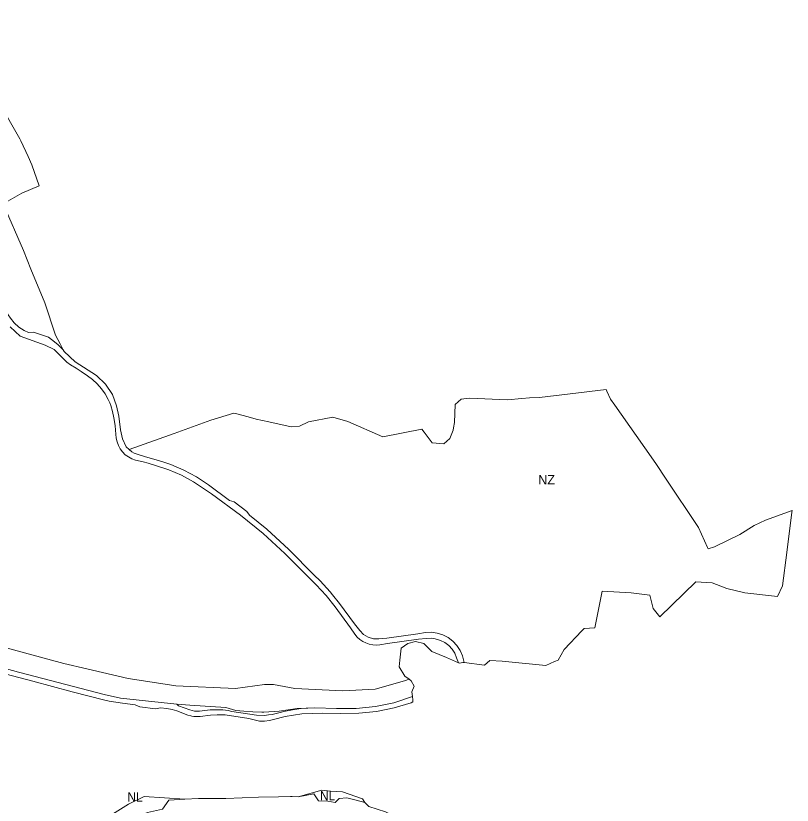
# Model space of a CAD drawing. Extents: x -650451 to -642268, y -1075216 to -1066610.
# Drawn here: x -645020 to -644023, y -1068995 to -1067980 of the extents above; entities that cross this region are included whole.
import ezdxf

# ---------------------------------------------------------------- set-up
doc = ezdxf.new("R2010")
doc.units = 0
doc.header["$LTSCALE"] = 4.8
for name, color, linetype, lineweight in [('15', 7, 'Continuous', 13), ('25', 7, 'Continuous', 13), ('45', 7, 'Continuous', 13), ('46', 7, 'Continuous', 13), ('47', 7, 'Continuous', 13), ('48', 7, 'Continuous', 13)]:
    doc.layers.add(name, color=color, linetype=linetype, lineweight=lineweight)
doc.layers.add('62', color=7, linetype='Continuous')

msp = doc.modelspace()

# ---------------------------------------------------------------- linework, layer by layer
at = {"layer": '15'}
for points in [[(-645212.831, -1068022.262), (-645216.33, -1068029.45), (-645210.19, -1068049.9), (-645200.78, -1068069.33), (-645154.68, -1068150.75), (-645140.99, -1068174.92), (-645123.29, -1068207.28), (-645106.55, -1068240.15), (-645098.61, -1068256.33), (-645091.6, -1068269.57), (-645083.99, -1068282.08), (-645035.86, -1068356.25), (-645030.2, -1068364.48), (-645027.23, -1068368.85), (-645022.34, -1068375.11), (-645016.44, -1068380.44), (-645009.72, -1068384.69), (-645003.98, -1068387.18), (-644997.7, -1068387.1), (-644978.39, -1068393.26), (-644970.72, -1068399.33), (-644966.17, -1068403.25), (-644959.42, -1068409.51)], [(-644451.72, -1068811.85), (-644454.22, -1068805.29), (-644456.69, -1068799.46), (-644460.09, -1068794.2), (-644464.36, -1068789.61), (-644469.35, -1068785.83), (-644474.92, -1068782.96), (-644481.87, -1068780.8), (-644487.12, -1068780.31), (-644493.45, -1068780.61), (-644503.36, -1068781.54), (-644543.14, -1068786.88), (-644553.01, -1068788.71), (-644557.54, -1068789.02), (-644562.07, -1068788.72), (-644566.53, -1068787.81), (-644570.82, -1068786.31), (-644574.88, -1068784.25), (-644578.63, -1068781.68), (-644582, -1068778.62), (-644584.92, -1068775.15), (-644590.45, -1068766.78), (-644610.23, -1068739.86), (-644621.86, -1068725.22), (-644634.57, -1068711.51), (-644674.76, -1068671.3), (-644702.58, -1068645.52), (-644731.96, -1068622.17), (-644769.24, -1068594.82), (-644783.35, -1068585.07), (-644792.14, -1068579.21), (-644807.7, -1068570.75), (-644823.96, -1068563.74), (-644840.81, -1068558.21), (-644850.38, -1068555.38), (-644857.02, -1068553.54), (-644866.81, -1068551.32), (-644871.47, -1068549.65), (-644875.84, -1068547.31), (-644879.83, -1068544.36), (-644883.35, -1068540.86), (-644886.32, -1068536.89), (-644888.68, -1068532.52), (-644890.38, -1068527.86), (-644891.38, -1068523.02), (-644892.19, -1068513.01), (-644893.01, -1068506.77), (-644894.55, -1068496.92), (-644896.06, -1068488.82), (-644898.42, -1068480.97), (-644899.73, -1068477.88), (-644901.61, -1068473.42), (-644905.59, -1068466.26), (-644910.32, -1068459.56), (-644915.73, -1068453.41), (-644921.78, -1068447.88), (-644928.42, -1068443), (-644936.62, -1068437.33), (-644942.9, -1068433.22), (-644950.19, -1068428.86), (-644954.98, -1068425.33), (-644959.35, -1068421.29), (-644971.12, -1068409.35), (-644982.58, -1068403.83), (-645014.95, -1068392.17), (-645027.82, -1068380.21)], [(-644959.42, -1068409.51), (-644958.31, -1068411.62), (-644944.04, -1068424.83), (-644916.66, -1068442.76), (-644905.1, -1068453.62), (-644896.42, -1068467.11), (-644890.97, -1068481.37), (-644887.96, -1068495.04), (-644885.79, -1068512.56), (-644883.53, -1068523.78), (-644878.8, -1068534.32), (-644874.91, -1068537.88)], [(-644874.91, -1068537.88), (-644871.56, -1068540.55), (-644868.22, -1068542.34), (-644864.59, -1068543.64), (-644855.14, -1068546.79), (-644838.81, -1068551.19), (-644830.39, -1068553.95), (-644821.37, -1068556.91), (-644804.51, -1068564.19), (-644788.37, -1068572.95), (-644773.09, -1068583.13), (-644746.05, -1068603), (-644740.04, -1068604.99), (-644723.76, -1068617.16), (-644720.27, -1068622.19), (-644698.01, -1068640.21), (-644669.84, -1068666.32), (-644637.12, -1068699.06), (-644629.59, -1068706.59), (-644616.55, -1068720.66), (-644613.59, -1068724.38), (-644604.61, -1068735.68), (-644585.48, -1068761.72), (-644578.54, -1068770.34), (-644573.66, -1068775.4), (-644567.69, -1068778.94), (-644561, -1068780.78), (-644553.97, -1068780.77), (-644544.07, -1068779.94), (-644504.29, -1068774.6), (-644494.4, -1068772.87), (-644486.81, -1068772.51), (-644479.25, -1068773.48), (-644471.97, -1068775.73), (-644465.19, -1068779.22), (-644459.12, -1068783.82), (-644453.93, -1068789.41), (-644449.79, -1068795.8), (-644446.83, -1068802.8), (-644444.48, -1068811.47)], [(-645052.77, -1068813.81), (-645016.93, -1068823.91), (-644907.14, -1068852.58), (-644886.04, -1068857.02), (-644833.88, -1068862.85), (-644813.66, -1068865.1)], [(-644444.48, -1068811.47), (-644446.04, -1068811.26), (-644446.38, -1068811.43), (-644450.57, -1068812.38), (-644451.72, -1068811.85)], [(-644510.37, -1068861.95), (-644512.71, -1068863.06), (-644534.67, -1068869.62), (-644557.21, -1068874.19), (-644580.06, -1068876.69), (-644602.97, -1068877.11), (-644626.34, -1068876.48), (-644653.09, -1068877.33), (-644674.5, -1068880.97), (-644689.63, -1068884.43), (-644694.39, -1068886.08), (-644700.83, -1068886.97), (-644707.32, -1068886.63), (-644721.29, -1068883.2), (-644751.36, -1068878.76), (-644753.71, -1068878.41), (-644761.63, -1068878.43), (-644770.17, -1068879.01), (-644783.84, -1068880.69), (-644787.7, -1068880.94), (-644791.66, -1068880.72), (-644794.33, -1068880.25), (-644795.57, -1068880.03), (-644799.27, -1068878.92), (-644813.52, -1068873.69), (-644819.79, -1068871.79), (-644826.24, -1068870.62), (-644834.48, -1068869.6), (-644840.86, -1068870.9), (-644861.04, -1068868.43), (-644867.05, -1068865.58), (-644883.44, -1068863.56), (-644900.37, -1068860.89), (-644906.18, -1068859.57), (-644947.96, -1068848.91), (-644998.7, -1068835.48), (-645059.46, -1068819.41)], [(-644636.47, -1068869.57), (-644608.6, -1068870.65), (-644583.36, -1068870.34), (-644558.29, -1068867.94), (-644535.08, -1068863.04), (-644511.02, -1068855.06)], [(-644511.02, -1068855.06), (-644510.62, -1068859.35), (-644510.37, -1068861.95)], [(-644813.66, -1068865.1), (-644811.3, -1068867.05), (-644797.05, -1068872.28), (-644793.95, -1068873.21), (-644790.86, -1068873.75), (-644787.73, -1068873.92), (-644784.49, -1068873.72), (-644770.84, -1068872.04), (-644761.64, -1068872.02), (-644754.65, -1068872.35), (-644747.68, -1068873.15), (-644742.79, -1068874.23), (-644711.22, -1068878.96), (-644701.15, -1068879.47), (-644696.09, -1068878.77), (-644691.16, -1068878.11), (-644680.88, -1068875.66), (-644676.04, -1068874.35), (-644664.98, -1068872.09), (-644653.78, -1068870.56), (-644636.47, -1068869.57)]]:
    msp.add_lwpolyline(points, dxfattribs=at)
at = {"layer": '25'}
for points in [[(-644952.47, -1069036.35), (-644944.9, -1069035.04), (-644925.35, -1069027.75), (-644871.42, -1069012.51), (-644851.16, -1069004.21), (-644831.81, -1068999.68), (-644824.07, -1068988.08), (-644803.31, -1068986.97)], [(-644803.31, -1068986.97), (-644785.78, -1068986.13), (-644761.88, -1068986.27), (-644750.67, -1068986.34), (-644708.6, -1068984.54), (-644683, -1068984.03), (-644667.57, -1068983.47), (-644665.41, -1068983.39), (-644657.61, -1068983.91)], [(-644657.61, -1068983.91), (-644637.75, -1068980.06), (-644631.77, -1068989.32), (-644619.63, -1068989.55), (-644610.36, -1068991.39), (-644605.2, -1068986.06), (-644595.46, -1068985.35), (-644583.27, -1068988.28), (-644572.05, -1068991.08)], [(-644572.05, -1068991.08), (-644567.09, -1068996.26), (-644545.54, -1069003.12), (-644472.37, -1069041.44), (-644468.95, -1069043.11), (-644424.01, -1069065.01), (-644404.96, -1069071.76), (-644383.55, -1069076.57), (-644357.4, -1069079.84), (-644337.6, -1069081.29), (-644322.55, -1069080.62), (-644319.2, -1069079.82), (-644292.27, -1069076.05), (-644286.94, -1069073.19)]]:
    msp.add_lwpolyline(points, dxfattribs=at)
at = {"layer": '45'}
for points in [[(-645050.5, -1068788.01), (-645004.48, -1068800.3), (-644958.68, -1068812.54), (-644928.99, -1068819.58), (-644875.93, -1068832.15), (-644817.51, -1068840.81), (-644814.86, -1068841.2), (-644738.26, -1068844.61), (-644700.9, -1068839.57), (-644689.35, -1068839.45), (-644661.88, -1068844.68), (-644600.36, -1068847.65), (-644558.97, -1068845.61), (-644521.21, -1068834.8), (-644515.35, -1068832.94)], [(-644813.66, -1068865.1), (-644833.88, -1068862.85), (-644886.04, -1068857.02), (-644907.14, -1068852.58), (-645016.93, -1068823.91), (-645052.77, -1068813.81)], [(-644515.35, -1068832.94), (-644512.8, -1068834.77), (-644508.91, -1068841.71), (-644511.59, -1068849.1), (-644511.02, -1068855.06)], [(-644511.02, -1068855.06), (-644535.08, -1068863.04), (-644558.29, -1068867.94), (-644583.36, -1068870.34), (-644608.6, -1068870.65), (-644636.47, -1068869.57)], [(-644636.47, -1068869.57), (-644659.02, -1068870.36), (-644682.21, -1068873.77), (-644701.79, -1068875.14), (-644703.98, -1068875.29), (-644704.63, -1068875.27), (-644716.11, -1068874.86), (-644727.74, -1068874.05), (-644737.68, -1068872.87), (-644750.82, -1068869.4), (-644797.05, -1068866.35), (-644813.66, -1068865.1)]]:
    msp.add_lwpolyline(points, dxfattribs=at)
at = {"layer": '46'}
for points in [[(-645179.06, -1068007.39), (-645126.11, -1067986.52), (-645111.83, -1067980.38), (-645086.3, -1068021.92), (-645066.21, -1068054.16), (-645053.36, -1068077.25), (-645045.78, -1068087.19), (-645041.75, -1068092.48), (-645015.38, -1068138.59), (-645014.09, -1068140.85), (-645004.64, -1068161.3), (-644999.74, -1068171.88), (-644990.43, -1068198.75), (-645012.64, -1068208.23), (-645036.69, -1068221.92), (-645010.65, -1068282), (-645000.93, -1068306.11), (-644983.04, -1068349.19), (-644969.23, -1068390.78), (-644963.44, -1068401.84), (-644959.42, -1068409.51)], [(-644959.42, -1068409.51), (-644966.17, -1068403.25), (-644970.72, -1068399.33), (-644978.39, -1068393.26), (-644997.7, -1068387.1), (-645003.98, -1068387.18), (-645009.72, -1068384.69), (-645016.44, -1068380.44), (-645022.34, -1068375.11), (-645027.23, -1068368.85), (-645030.2, -1068364.48), (-645035.86, -1068356.25), (-645083.99, -1068282.08), (-645091.6, -1068269.57), (-645098.61, -1068256.33), (-645106.55, -1068240.15), (-645123.29, -1068207.28), (-645140.99, -1068174.92), (-645154.68, -1068150.75), (-645200.78, -1068069.33), (-645210.19, -1068049.9), (-645216.33, -1068029.45), (-645212.831, -1068022.262)], [(-645027.82, -1068380.21), (-645014.95, -1068392.17), (-644982.58, -1068403.83), (-644971.12, -1068409.35), (-644959.35, -1068421.29), (-644954.98, -1068425.33), (-644950.19, -1068428.86), (-644942.9, -1068433.22), (-644936.62, -1068437.33), (-644928.42, -1068443), (-644921.78, -1068447.88), (-644915.73, -1068453.41), (-644910.32, -1068459.56), (-644905.59, -1068466.26), (-644901.61, -1068473.42), (-644899.73, -1068477.88), (-644898.42, -1068480.97), (-644896.06, -1068488.82), (-644894.55, -1068496.92), (-644893.01, -1068506.77), (-644892.19, -1068513.01), (-644891.38, -1068523.02), (-644890.38, -1068527.86), (-644888.68, -1068532.52), (-644886.32, -1068536.89), (-644883.35, -1068540.86), (-644879.83, -1068544.36), (-644875.84, -1068547.31), (-644871.47, -1068549.65), (-644866.81, -1068551.32), (-644857.02, -1068553.54), (-644850.38, -1068555.38), (-644840.81, -1068558.21), (-644823.96, -1068563.74), (-644807.7, -1068570.75), (-644792.14, -1068579.21), (-644783.35, -1068585.07), (-644769.24, -1068594.82), (-644731.96, -1068622.17), (-644702.58, -1068645.52), (-644674.76, -1068671.3), (-644634.57, -1068711.51), (-644621.86, -1068725.22), (-644610.23, -1068739.86), (-644590.45, -1068766.78), (-644584.92, -1068775.15), (-644582, -1068778.62), (-644578.63, -1068781.68), (-644574.88, -1068784.25), (-644570.82, -1068786.31), (-644566.53, -1068787.81), (-644562.07, -1068788.72), (-644557.54, -1068789.02), (-644553.01, -1068788.71), (-644543.14, -1068786.88), (-644503.36, -1068781.54), (-644493.45, -1068780.61), (-644487.12, -1068780.31), (-644481.87, -1068780.8), (-644474.92, -1068782.96), (-644469.35, -1068785.83), (-644464.36, -1068789.61), (-644460.09, -1068794.2), (-644456.69, -1068799.46), (-644454.22, -1068805.29), (-644451.72, -1068811.85)], [(-644874.91, -1068537.88), (-644861.66, -1068533.12), (-644817.2, -1068517.16), (-644769.81, -1068500.14), (-644740.19, -1068490.94), (-644738.21, -1068491.47), (-644721.78, -1068495.91), (-644711.66, -1068498.64), (-644695.39, -1068502.2), (-644666.9, -1068508.43), (-644656.02, -1068507.74), (-644644.61, -1068502.27), (-644613.31, -1068496.32), (-644593.87, -1068501.49), (-644548.94, -1068521.25), (-644498.94, -1068511.55), (-644495.92, -1068515.56), (-644485.76, -1068529.02), (-644470.73, -1068530.25), (-644462.79, -1068523.43), (-644458.67, -1068512.97), (-644458.08, -1068509.68), (-644456.87, -1068502.9), (-644455.92, -1068479.77), (-644448.34, -1068472.84), (-644437.56, -1068471.74), (-644388.9, -1068473.85), (-644370.32, -1068472), (-644360.51, -1068471.42), (-644347.85, -1068470.66), (-644308.57, -1068466.06), (-644262.29, -1068460.65), (-644261.29, -1068462.8), (-644256.6, -1068472.93), (-644251.14, -1068480.71), (-644204.38, -1068547.31), (-644197.48, -1068557.14), (-644185.98, -1068574.33), (-644143.46, -1068637.9), (-644132.01, -1068663.82), (-644131.31, -1068665.41), (-644123.19, -1068662.91), (-644090.63, -1068647.07), (-644071.97, -1068635.37), (-644057.67, -1068628.58), (-644023.26, -1068616.04), (-644023.53, -1068618.11), (-644030.25, -1068670.09), (-644035.8, -1068713.05), (-644041.95, -1068726.74), (-644084.05, -1068721.94), (-644107.15, -1068716.43), (-644126.21, -1068709.11), (-644146.83, -1068707.59), (-644193.18, -1068752.57), (-644201.68, -1068742), (-644205.9, -1068724.81), (-644229.88, -1068721.73), (-644267.36, -1068719.64), (-644270.02, -1068732.67), (-644276.95, -1068766.66), (-644290.63, -1068767.86), (-644293.24, -1068770.61), (-644316.19, -1068794.85), (-644323.97, -1068808.35), (-644328.35, -1068810.2), (-644339.78, -1068815.02), (-644395.71, -1068809.61), (-644411.46, -1068808.85), (-644418.34, -1068814.9), (-644444.48, -1068811.47)], [(-644444.48, -1068811.47), (-644446.83, -1068802.8), (-644449.79, -1068795.8), (-644453.93, -1068789.41), (-644459.12, -1068783.82), (-644465.19, -1068779.22), (-644471.97, -1068775.73), (-644479.25, -1068773.48), (-644486.81, -1068772.51), (-644494.4, -1068772.87), (-644504.29, -1068774.6), (-644544.07, -1068779.94), (-644553.97, -1068780.77), (-644561, -1068780.78), (-644567.69, -1068778.94), (-644573.66, -1068775.4), (-644578.54, -1068770.34), (-644585.48, -1068761.72), (-644604.61, -1068735.68), (-644613.59, -1068724.38), (-644616.55, -1068720.66), (-644629.59, -1068706.59), (-644637.12, -1068699.06), (-644669.84, -1068666.32), (-644698.01, -1068640.21), (-644720.27, -1068622.19), (-644723.76, -1068617.16), (-644740.04, -1068604.99), (-644746.05, -1068603), (-644773.09, -1068583.13), (-644788.37, -1068572.95), (-644804.51, -1068564.19), (-644821.37, -1068556.91), (-644830.39, -1068553.95), (-644838.81, -1068551.19), (-644855.14, -1068546.79), (-644864.59, -1068543.64), (-644868.22, -1068542.34), (-644871.56, -1068540.55), (-644874.91, -1068537.88)], [(-644451.72, -1068811.85), (-644467.09, -1068804.79), (-644485.91, -1068797.32), (-644496.54, -1068786.91), (-644507.08, -1068784.53), (-644516.93, -1068786.93), (-644525.55, -1068792.76), (-644527.14, -1068808.54), (-644527.98, -1068816.8), (-644520.94, -1068828.93), (-644515.35, -1068832.94)], [(-644515.35, -1068832.94), (-644521.21, -1068834.8), (-644558.97, -1068845.61), (-644600.36, -1068847.65), (-644661.88, -1068844.68), (-644689.35, -1068839.45), (-644700.9, -1068839.57), (-644738.26, -1068844.61), (-644814.86, -1068841.2), (-644817.51, -1068840.81), (-644875.93, -1068832.15), (-644928.99, -1068819.58), (-644958.68, -1068812.54), (-645004.48, -1068800.3), (-645050.5, -1068788.01)]]:
    msp.add_lwpolyline(points, dxfattribs=at)
at = {"layer": '47'}
for points in [[(-644657.61, -1068983.91), (-644627.41, -1068975.6), (-644616.36, -1068976.86), (-644600.67, -1068977.77), (-644575.29, -1068986.48), (-644572.05, -1068991.08)], [(-644952.47, -1069036.35), (-644918.04, -1069020.91), (-644903.21, -1069010.69), (-644875.57, -1068993.47), (-644855.56, -1068983.38), (-644803.31, -1068986.97)], [(-644803.31, -1068986.97), (-644824.07, -1068988.08), (-644831.81, -1068999.68), (-644851.16, -1069004.21), (-644871.42, -1069012.51), (-644925.35, -1069027.75), (-644944.9, -1069035.04), (-644952.47, -1069036.35)], [(-644572.05, -1068991.08), (-644583.27, -1068988.28), (-644595.46, -1068985.35), (-644605.2, -1068986.06), (-644610.36, -1068991.39), (-644619.63, -1068989.55), (-644631.77, -1068989.32), (-644637.75, -1068980.06), (-644657.61, -1068983.91)]]:
    msp.add_lwpolyline(points, dxfattribs=at)
at = {"layer": '48'}
for points in [[(-644813.66, -1068865.1), (-644797.05, -1068866.35), (-644750.82, -1068869.4), (-644737.68, -1068872.87), (-644727.74, -1068874.05), (-644716.11, -1068874.86), (-644704.63, -1068875.27), (-644703.98, -1068875.29), (-644701.79, -1068875.14), (-644682.21, -1068873.77), (-644659.02, -1068870.36), (-644636.47, -1068869.57)], [(-644636.47, -1068869.57), (-644653.78, -1068870.56), (-644664.98, -1068872.09), (-644676.04, -1068874.35), (-644680.88, -1068875.66), (-644691.16, -1068878.11), (-644696.09, -1068878.77), (-644701.15, -1068879.47), (-644711.22, -1068878.96), (-644742.79, -1068874.23), (-644747.68, -1068873.15), (-644754.65, -1068872.35), (-644761.64, -1068872.02), (-644770.84, -1068872.04), (-644784.49, -1068873.72), (-644787.73, -1068873.92), (-644790.86, -1068873.75), (-644793.95, -1068873.21), (-644797.05, -1068872.28), (-644811.3, -1068867.05), (-644813.66, -1068865.1)]]:
    msp.add_lwpolyline(points, dxfattribs=at)

# ---------------------------------------------------------------- texts
at = {"layer": '62'}
msp.add_text('NZ', height=12, dxfattribs=at).set_placement((-644349.418, -1068582.615))
at = {"layer": '62', "width": 0.95}
for p in [(-644877.075, -1068990.181), (-644629.668, -1068988.696)]:
    msp.add_text('NL', height=12, dxfattribs=at).set_placement(p)

doc.saveas('drawing.dxf')
